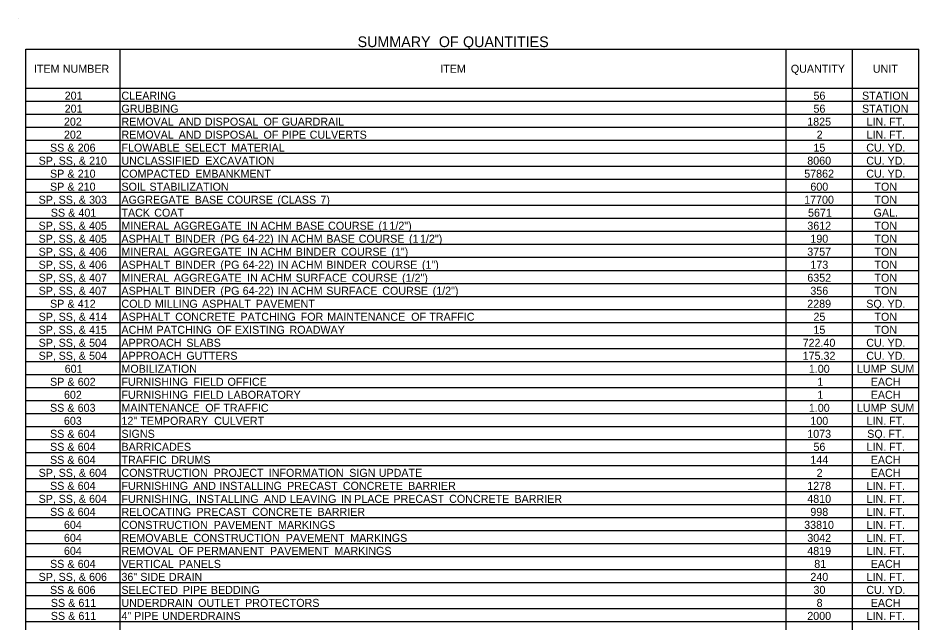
# Model space of a CAD drawing. Extents: x 977434 to 989596, y 1525697 to 1528336.
# Drawn here: x 988121 to 988796, y 1527868 to 1528322 of the extents above; entities that cross this region are included whole.
import ezdxf

# ---------------------------------------------------------------- set-up
doc = ezdxf.new("R2010")
doc.units = 0
doc.layers.add('Default', color=7, linetype='Continuous')
doc.layers.add('R_Border Prem', color=7, linetype='Continuous')

msp = doc.modelspace()

# ---------------------------------------------------------------- linework, layer by layer
at = {"layer": 'Default'}
for p, q in [((988126.95, 1528298.42), (988197.64, 1528298.42)), ((988126.95, 1528298.42), (988796.29, 1528298.42)), ((988126.95, 1527411.17), (988126.95, 1528298.42)), ((988126.95, 1527411.17), (988126.95, 1528298.42)), ((988197.64, 1527625.67), (988197.64, 1528298.42)), ((988696.84, 1527411.17), (988696.84, 1528298.42)), ((988746.57, 1527411.17), (988746.57, 1528298.42)), ((988746.57, 1527625.67), (988746.57, 1528298.42)), ((988796.29, 1527411.17), (988796.29, 1528298.42)), ((988126.95, 1528269.17), (988796.29, 1528269.17)), ((988197.64, 1527625.67), (988197.64, 1528269.17)), ((988696.84, 1527625.67), (988696.84, 1528269.17)), ((988126.95, 1528259.42), (988796.29, 1528259.42)), ((988126.95, 1528249.67), (988796.29, 1528249.67)), ((988126.95, 1528239.92), (988796.29, 1528239.92)), ((988126.95, 1528230.17), (988796.29, 1528230.17)), ((988126.95, 1528220.42), (988796.29, 1528220.42)), ((988126.95, 1528210.67), (988796.29, 1528210.67)), ((988126.95, 1528200.92), (988796.29, 1528200.92)), ((988126.95, 1528191.17), (988796.29, 1528191.17)), ((988126.95, 1528181.42), (988796.29, 1528181.42)), ((988126.95, 1528171.67), (988796.29, 1528171.67)), ((988126.95, 1528161.92), (988796.29, 1528161.92)), ((988126.95, 1528152.17), (988796.29, 1528152.17)), ((988126.95, 1528142.42), (988796.29, 1528142.42)), ((988126.95, 1528132.67), (988796.29, 1528132.67)), ((988126.95, 1528122.92), (988796.29, 1528122.92)), ((988126.95, 1528113.17), (988796.29, 1528113.17)), ((988126.95, 1528103.42), (988796.29, 1528103.42)), ((988126.95, 1528093.67), (988796.29, 1528093.67)), ((988126.95, 1528083.92), (988796.29, 1528083.92)), ((988126.95, 1528074.17), (988796.29, 1528074.17)), ((988126.95, 1528064.42), (988796.29, 1528064.42)), ((988126.95, 1528054.67), (988796.29, 1528054.67)), ((988126.95, 1528044.92), (988796.29, 1528044.92)), ((988126.95, 1528035.17), (988796.29, 1528035.17)), ((988126.95, 1528025.42), (988796.29, 1528025.42)), ((988126.95, 1528015.67), (988796.29, 1528015.67)), ((988126.95, 1528005.92), (988796.29, 1528005.92)), ((988126.95, 1527996.17), (988796.29, 1527996.17)), ((988126.95, 1527986.42), (988796.29, 1527986.42)), ((988126.95, 1527976.67), (988796.29, 1527976.67)), ((988126.95, 1527966.92), (988796.29, 1527966.92)), ((988126.95, 1527957.17), (988796.29, 1527957.17)), ((988126.95, 1527947.42), (988796.29, 1527947.42)), ((988126.95, 1527937.67), (988796.29, 1527937.67)), ((988126.95, 1527927.92), (988796.29, 1527927.92)), ((988126.95, 1527918.17), (988796.29, 1527918.17)), ((988126.95, 1527908.42), (988796.29, 1527908.42)), ((988126.95, 1527898.67), (988796.29, 1527898.67)), ((988126.95, 1527888.92), (988796.29, 1527888.92)), ((988126.95, 1527879.17), (988796.29, 1527879.17)), ((988126.95, 1527869.42), (988796.29, 1527869.42))]:
    msp.add_line(p, q, dxfattribs=at)
at = {"layer": 'R_Border Prem'}
msp.add_line((988121.1, 1528321.82), (988121.1, 1528321.82), dxfattribs=at)

# ---------------------------------------------------------------- texts
at = {"layer": 'Default'}
for s, height, p in [(' SUMMARY', 8, (988372.62, 1528300.02)), (' OF', 8, (988433.5, 1528300.02)), (' QUANTITIES', 8, (988451.61, 1528300.02)), ('ITEM', 6, (988133.04, 1528280.8)), (' NUMBER', 6, (988152.47, 1528280.8)), ('ITEM', 6, (988437.53, 1528280.8)), ('QUANTITY', 6, (988700.27, 1528280.8)), ('UNIT', 6, (988761.74, 1528280.8)), ('201', 6, (988156.08, 1528260.62)), ('CLEARING', 6, (988198.62, 1528260.62)), ('56', 6, (988717.23, 1528260.62)), ('STATION', 6, (988753.6, 1528260.62)), ('201', 6, (988156.08, 1528250.87)), ('GRUBBING', 6, (988198.62, 1528250.87)), ('56', 6, (988717.23, 1528250.87)), ('STATION', 6, (988753.6, 1528250.87)), ('202', 6, (988155.53, 1528241.12)), ('REMOVAL', 6, (988198.62, 1528241.12)), (' AND', 6, (988239.32, 1528241.12)), (' DISPOSAL', 6, (988258.9, 1528241.12)), (' OF', 6, (988302.87, 1528241.12)), (' GUARDRAIL', 6, (988316.45, 1528241.12)), ('1825', 6, (988712.55, 1528241.12)), ('LIN.', 6, (988757.03, 1528241.12)), (' FT.', 6, (988771.66, 1528241.12)), ('202', 6, (988155.53, 1528231.37)), ('REMOVAL', 6, (988198.62, 1528231.37)), (' AND', 6, (988239.32, 1528231.37)), (' DISPOSAL', 6, (988258.9, 1528231.37)), (' OF', 6, (988302.87, 1528231.37)), (' PIPE', 6, (988316.45, 1528231.37)), (' CULVERTS', 6, (988337.44, 1528231.37)), ('2', 6, (988719.6, 1528231.37)), ('LIN.', 6, (988757.03, 1528231.37)), (' FT.', 6, (988771.66, 1528231.37)), ('SS', 6, (988145.1, 1528221.62)), (' &', 6, (988155.84, 1528221.62)), (' 206', 6, (988163.57, 1528221.62)), ('FLOWABLE', 6, (988198.62, 1528221.62)), (' SELECT', 6, (988243.82, 1528221.62)), (' MATERIAL', 6, (988278.6, 1528221.62)), ('15', 6, (988717.21, 1528221.62)), ('CU.', 6, (988756.79, 1528221.62)), (' YD.', 6, (988770.5, 1528221.62)), ('SP,', 6, (988136.55, 1528211.87)), (' SS,', 6, (988149.32, 1528211.87)), (' &', 6, (988164.41, 1528211.87)), (' 210', 6, (988172.14, 1528211.87)), ('UNCLASSIFIED', 6, (988198.62, 1528211.87)), (' EXCAVATION', 6, (988259.2, 1528211.87)), ('8060', 6, (988712.58, 1528211.87)), ('CU.', 6, (988756.79, 1528211.87)), (' YD.', 6, (988770.5, 1528211.87)), ('SP', 6, (988145.07, 1528202.12)), (' &', 6, (988155.89, 1528202.12)), (' 210', 6, (988163.62, 1528202.12)), ('COMPACTED', 6, (988198.62, 1528202.12)), (' EMBANKMENT', 6, (988251.74, 1528202.12)), ('57862', 6, (988710.28, 1528202.12)), ('CU.', 6, (988756.79, 1528202.12)), (' YD.', 6, (988770.5, 1528202.12)), ('SP', 6, (988145.07, 1528192.37)), (' &', 6, (988155.89, 1528192.37)), (' 210', 6, (988163.62, 1528192.37)), ('SOIL', 6, (988198.62, 1528192.37)), (' STABILIZATION', 6, (988217.42, 1528192.37)), ('600', 6, (988714.91, 1528192.37)), ('TON', 6, (988762.92, 1528192.37)), ('SP,', 6, (988136.54, 1528182.62)), (' SS,', 6, (988149.3, 1528182.62)), (' &', 6, (988164.4, 1528182.62)), (' 303', 6, (988172.13, 1528182.62)), ('AGGREGATE', 6, (988198.62, 1528182.62)), (' BASE', 6, (988251.28, 1528182.62)), (' COURSE', 6, (988275.53, 1528182.62)), (' (CLASS', 6, (988313.28, 1528182.62)), (' 7)', 6, (988345.46, 1528182.62)), ('17700', 6, (988710.25, 1528182.62)), ('TON', 6, (988762.92, 1528182.62)), ('SS', 6, (988145.68, 1528172.87)), (' &', 6, (988156.42, 1528172.87)), (' 401', 6, (988164.15, 1528172.87)), ('TACK', 6, (988198.62, 1528172.87)), (' COAT', 6, (988220.96, 1528172.87)), ('5671', 6, (988713.15, 1528172.87)), ('GAL.', 6, (988762.24, 1528172.87)), ('SP,', 6, (988136.51, 1528163.12)), (' SS,', 6, (988149.28, 1528163.12)), (' &', 6, (988164.38, 1528163.12)), (' 405', 6, (988172.11, 1528163.12)), ('MINERAL', 6, (988198.62, 1528163.12)), (' AGGREGATE', 6, (988235.59, 1528163.12)), (' IN', 6, (988290.58, 1528163.12)), (' ACHM', 6, (988300.6, 1528163.12)), (' BASE', 6, (988326.98, 1528163.12)), (' COURSE', 6, (988351.24, 1528163.12)), (' (1', 6, (988388.99, 1528163.12)), (' 1/2")', 6, (988397.22, 1528163.12)), ('3612', 6, (988712.61, 1528163.12)), ('TON', 6, (988762.92, 1528163.12)), ('SP,', 6, (988136.51, 1528153.37)), (' SS,', 6, (988149.28, 1528153.37)), (' &', 6, (988164.38, 1528153.37)), (' 405', 6, (988172.11, 1528153.37)), ('ASPHALT', 6, (988198.62, 1528153.37)), (' BINDER', 6, (988236.66, 1528153.37)), (' (PG', 6, (988270.55, 1528153.37)), (' 64-22)', 6, (988287.25, 1528153.37)), (' IN', 6, (988313.5, 1528153.37)), (' ACHM', 6, (988323.52, 1528153.37)), (' BASE', 6, (988349.91, 1528153.37)), (' COURSE', 6, (988374.16, 1528153.37)), (' (1', 6, (988411.91, 1528153.37)), (' 1/2")', 6, (988420.14, 1528153.37)), ('190', 6, (988714.91, 1528153.37)), ('TON', 6, (988762.92, 1528153.37)), ('SP,', 6, (988136.54, 1528143.62)), (' SS,', 6, (988149.3, 1528143.62)), (' &', 6, (988164.4, 1528143.62)), (' 406', 6, (988172.13, 1528143.62)), ('MINERAL', 6, (988198.62, 1528143.62)), (' AGGREGATE', 6, (988235.59, 1528143.62)), (' IN', 6, (988290.58, 1528143.62)), (' ACHM', 6, (988300.6, 1528143.62)), (' BINDER', 6, (988326.98, 1528143.62)), (' COURSE', 6, (988360.88, 1528143.62)), (' (1")', 6, (988398.63, 1528143.62)), ('3757', 6, (988712.57, 1528143.62)), ('TON', 6, (988762.92, 1528143.62)), ('SP,', 6, (988136.54, 1528133.87)), (' SS,', 6, (988149.3, 1528133.87)), (' &', 6, (988164.4, 1528133.87)), (' 406', 6, (988172.13, 1528133.87)), ('ASPHALT', 6, (988198.62, 1528133.87)), (' BINDER', 6, (988236.66, 1528133.87)), (' (PG', 6, (988270.55, 1528133.87)), (' 64-22)', 6, (988287.25, 1528133.87)), (' IN', 6, (988313.5, 1528133.87)), (' ACHM', 6, (988323.52, 1528133.87)), (' BINDER', 6, (988349.91, 1528133.87)), (' COURSE', 6, (988383.8, 1528133.87)), (' (1")', 6, (988421.55, 1528133.87)), ('173', 6, (988714.9, 1528133.87)), ('TON', 6, (988762.92, 1528133.87)), ('SP,', 6, (988136.54, 1528124.12)), (' SS,', 6, (988149.3, 1528124.12)), (' &', 6, (988164.4, 1528124.12)), (' 407', 6, (988172.13, 1528124.12)), ('MINERAL', 6, (988198.62, 1528124.12)), (' AGGREGATE', 6, (988235.59, 1528124.12)), (' IN', 6, (988290.58, 1528124.12)), (' ACHM', 6, (988300.6, 1528124.12)), (' SURFACE', 6, (988326.98, 1528124.12)), (' COURSE', 6, (988368.93, 1528124.12)), (' (1/2")', 6, (988406.68, 1528124.12)), ('6352', 6, (988712.61, 1528124.12)), ('TON', 6, (988762.92, 1528124.12)), ('SP,', 6, (988136.54, 1528114.37)), (' SS,', 6, (988149.3, 1528114.37)), (' &', 6, (988164.4, 1528114.37)), (' 407', 6, (988172.13, 1528114.37)), ('ASPHALT', 6, (988198.62, 1528114.37)), (' BINDER', 6, (988236.66, 1528114.37)), (' (PG', 6, (988270.55, 1528114.37)), (' 64-22)', 6, (988287.25, 1528114.37)), (' IN', 6, (988313.5, 1528114.37)), (' ACHM', 6, (988323.52, 1528114.37)), (' SURFACE', 6, (988349.91, 1528114.37)), (' COURSE', 6, (988391.85, 1528114.37)), (' (1/2")', 6, (988429.6, 1528114.37)), ('356', 6, (988714.9, 1528114.37)), ('TON', 6, (988762.92, 1528114.37)), ('SP', 6, (988145.09, 1528104.62)), (' &', 6, (988155.91, 1528104.62)), (' 412', 6, (988163.64, 1528104.62)), ('COLD', 6, (988198.62, 1528104.62)), (' MILLING', 6, (988221.46, 1528104.62)), (' ASPHALT', 6, (988256.8, 1528104.62)), (' PAVEMENT', 6, (988297.16, 1528104.62)), ('2289', 6, (988712.57, 1528104.62)), ('SQ.', 6, (988756.79, 1528104.62)), (' YD.', 6, (988770.5, 1528104.62)), ('SP,', 6, (988136.55, 1528094.87)), (' SS,', 6, (988149.32, 1528094.87)), (' &', 6, (988164.41, 1528094.87)), (' 414', 6, (988172.14, 1528094.87)), ('ASPHALT', 6, (988198.62, 1528094.87)), (' CONCRETE', 6, (988236.66, 1528094.87)), (' PATCHING', 6, (988285.58, 1528094.87)), (' FOR', 6, (988330.71, 1528094.87)), (' MAINTENANCE', 6, (988350.62, 1528094.87)), (' OF', 6, (988413.52, 1528094.87)), (' TRAFFIC', 6, (988427.11, 1528094.87)), ('25', 6, (988717.21, 1528094.87)), ('TON', 6, (988762.92, 1528094.87)), ('SP,', 6, (988136.51, 1528085.12)), (' SS,', 6, (988149.28, 1528085.12)), (' &', 6, (988164.38, 1528085.12)), (' 415', 6, (988172.11, 1528085.12)), ('ACHM', 6, (988198.62, 1528085.12)), (' PATCHING', 6, (988222.67, 1528085.12)), (' OF', 6, (988267.79, 1528085.12)), (' EXISTING', 6, (988281.38, 1528085.12)), (' ROADWAY', 6, (988322.32, 1528085.12)), ('15', 6, (988717.21, 1528085.12)), ('TON', 6, (988762.92, 1528085.12)), ('SP,', 6, (988136.55, 1528075.37)), (' SS,', 6, (988149.32, 1528075.37)), (' &', 6, (988164.41, 1528075.37)), (' 504', 6, (988172.14, 1528075.37)), ('APPROACH', 6, (988198.62, 1528075.37)), (' SLABS', 6, (988245, 1528075.37)), ('722.40', 6, (988709.09, 1528075.37)), ('CU.', 6, (988756.79, 1528075.37)), (' YD.', 6, (988770.5, 1528075.37)), ('SP,', 6, (988136.55, 1528065.62)), (' SS,', 6, (988149.32, 1528065.62)), (' &', 6, (988164.41, 1528065.62)), (' 504', 6, (988172.14, 1528065.62)), ('APPROACH', 6, (988198.62, 1528065.62)), (' GUTTERS', 6, (988245, 1528065.62)), ('175.32', 6, (988709.11, 1528065.62)), ('CU.', 6, (988756.79, 1528065.62)), (' YD.', 6, (988770.5, 1528065.62)), ('601', 6, (988156.08, 1528055.87)), ('MOBILIZATION', 6, (988198.62, 1528055.87)), ('1.00', 6, (988713.75, 1528055.87)), ('LUMP', 6, (988749.8, 1528055.87)), (' SUM', 6, (988772.73, 1528055.87)), ('SP', 6, (988145.09, 1528046.12)), (' &', 6, (988155.91, 1528046.12)), (' 602', 6, (988163.64, 1528046.12)), ('FURNISHING', 6, (988198.62, 1528046.12)), (' FIELD', 6, (988250.26, 1528046.12)), (' OFFICE', 6, (988275.89, 1528046.12)), ('1', 6, (988720.14, 1528046.12)), ('EACH', 6, (988760.12, 1528046.12)), ('602', 6, (988155.53, 1528036.37)), ('FURNISHING', 6, (988198.62, 1528036.37)), (' FIELD', 6, (988250.26, 1528036.37)), (' LABORATORY', 6, (988275.89, 1528036.37)), ('1', 6, (988720.14, 1528036.37)), ('EACH', 6, (988760.12, 1528036.37)), ('SS', 6, (988145.1, 1528026.62)), (' &', 6, (988155.84, 1528026.62)), (' 603', 6, (988163.57, 1528026.62)), ('MAINTENANCE', 6, (988198.62, 1528026.62)), (' OF', 6, (988259.19, 1528026.62)), (' TRAFFIC', 6, (988272.78, 1528026.62)), ('1.00', 6, (988713.75, 1528026.62)), ('LUMP', 6, (988749.8, 1528026.62)), (' SUM', 6, (988772.73, 1528026.62)), ('603', 6, (988155.5, 1528016.87)), ('12"', 6, (988198.62, 1528016.87)), (' TEMPORARY', 6, (988210.52, 1528016.87)), (' CULVERT', 6, (988265.89, 1528016.87)), ('100', 6, (988714.91, 1528016.87)), ('LIN.', 6, (988757.03, 1528016.87)), (' FT.', 6, (988771.66, 1528016.87)), ('SS', 6, (988145.11, 1528007.12)), (' &', 6, (988155.86, 1528007.12)), (' 604', 6, (988163.58, 1528007.12)), ('SIGNS', 6, (988198.62, 1528007.12)), ('1073', 6, (988712.57, 1528007.12)), ('SQ.', 6, (988757.49, 1528007.12)), (' FT.', 6, (988771.2, 1528007.12)), ('SS', 6, (988145.11, 1527997.37)), (' &', 6, (988155.86, 1527997.37)), (' 604', 6, (988163.58, 1527997.37)), ('BARRICADES', 6, (988198.62, 1527997.37)), ('56', 6, (988717.23, 1527997.37)), ('LIN.', 6, (988757.03, 1527997.37)), (' FT.', 6, (988771.66, 1527997.37)), ('SS', 6, (988145.11, 1527987.62)), (' &', 6, (988155.86, 1527987.62)), (' 604', 6, (988163.58, 1527987.62)), ('TRAFFIC', 6, (988198.62, 1527987.62)), (' DRUMS', 6, (988233.68, 1527987.62)), ('144', 6, (988714.92, 1527987.62)), ('EACH', 6, (988760.12, 1527987.62)), ('SP,', 6, (988136.55, 1527977.87)), (' SS,', 6, (988149.32, 1527977.87)), (' &', 6, (988164.41, 1527977.87)), (' 604', 6, (988172.14, 1527977.87)), ('CONSTRUCTION', 6, (988198.62, 1527977.87)), (' PROJECT', 6, (988265.47, 1527977.87)), (' INFORMATION', 6, (988306.76, 1527977.87)), (' SIGN', 6, (988367.08, 1527977.87)), (' UPDATE', 6, (988389.22, 1527977.87)), ('2', 6, (988719.6, 1527977.87)), ('EACH', 6, (988760.12, 1527977.87)), ('SS', 6, (988145.11, 1527968.12)), (' &', 6, (988155.86, 1527968.12)), (' 604', 6, (988163.58, 1527968.12)), ('FURNISHING', 6, (988198.62, 1527968.12)), (' AND', 6, (988250.26, 1527968.12)), (' INSTALLING', 6, (988269.84, 1527968.12)), (' PRECAST', 6, (988320.55, 1527968.12)), (' CONCRETE', 6, (988362.32, 1527968.12)), (' BARRIER', 6, (988411.25, 1527968.12)), ('1278', 6, (988712.57, 1527968.12)), ('LIN.', 6, (988757.03, 1527968.12)), (' FT.', 6, (988771.66, 1527968.12)), ('SP,', 6, (988136.55, 1527958.37)), (' SS,', 6, (988149.32, 1527958.37)), (' &', 6, (988164.41, 1527958.37)), (' 604', 6, (988172.14, 1527958.37)), ('FURNISHING,', 6, (988198.62, 1527958.37)), (' INSTALLING', 6, (988252.36, 1527958.37)), (' AND', 6, (988303.08, 1527958.37)), (' LEAVING', 6, (988322.66, 1527958.37)), (' IN', 6, (988360.81, 1527958.37)), (' PLACE', 6, (988370.83, 1527958.37)), (' PRECAST', 6, (988400.21, 1527958.37)), (' CONCRETE', 6, (988441.97, 1527958.37)), (' BARRIER', 6, (988490.9, 1527958.37)), ('4810', 6, (988712.58, 1527958.37)), ('LIN.', 6, (988757.03, 1527958.37)), (' FT.', 6, (988771.66, 1527958.37)), ('SS', 6, (988145.11, 1527948.62)), (' &', 6, (988155.86, 1527948.62)), (' 604', 6, (988163.58, 1527948.62)), ('RELOCATING', 6, (988198.62, 1527948.62)), (' PRECAST', 6, (988252.59, 1527948.62)), (' CONCRETE', 6, (988294.36, 1527948.62)), (' BARRIER', 6, (988343.28, 1527948.62)), ('998', 6, (988714.9, 1527948.62)), ('LIN.', 6, (988757.03, 1527948.62)), (' FT.', 6, (988771.66, 1527948.62)), ('604', 6, (988155.51, 1527938.87)), ('CONSTRUCTION', 6, (988198.62, 1527938.87)), (' PAVEMENT', 6, (988265.47, 1527938.87)), (' MARKINGS', 6, (988313.75, 1527938.87)), ('33810', 6, (988710.25, 1527938.87)), ('LIN.', 6, (988757.03, 1527938.87)), (' FT.', 6, (988771.66, 1527938.87)), ('604', 6, (988155.51, 1527929.12)), ('REMOVABLE', 6, (988198.62, 1527929.12)), (' CONSTRUCTION', 6, (988250.35, 1527929.12)), (' PAVEMENT', 6, (988319.53, 1527929.12)), (' MARKINGS', 6, (988367.81, 1527929.12)), ('3042', 6, (988712.61, 1527929.12)), ('LIN.', 6, (988757.03, 1527929.12)), (' FT.', 6, (988771.66, 1527929.12)), ('604', 6, (988155.51, 1527919.37)), ('REMOVAL', 6, (988198.62, 1527919.37)), (' OF', 6, (988239.32, 1527919.37)), (' PERMANENT', 6, (988252.9, 1527919.37)), (' PAVEMENT', 6, (988307.7, 1527919.37)), (' MARKINGS', 6, (988355.99, 1527919.37)), ('4819', 6, (988712.57, 1527919.37)), ('LIN.', 6, (988757.03, 1527919.37)), (' FT.', 6, (988771.66, 1527919.37)), ('SS', 6, (988145.11, 1527909.62)), (' &', 6, (988155.86, 1527909.62)), (' 604', 6, (988163.58, 1527909.62)), ('VERTICAL', 6, (988198.62, 1527909.62)), (' PANELS', 6, (988239.32, 1527909.62)), ('81', 6, (988717.81, 1527909.62)), ('EACH', 6, (988760.12, 1527909.62)), ('SP,', 6, (988136.54, 1527899.87)), (' SS,', 6, (988149.3, 1527899.87)), (' &', 6, (988164.4, 1527899.87)), (' 606', 6, (988172.13, 1527899.87)), ('36"', 6, (988198.62, 1527899.87)), (' SIDE', 6, (988210.52, 1527899.87)), (' DRAIN', 6, (988231.97, 1527899.87)), ('240', 6, (988714.91, 1527899.87)), ('LIN.', 6, (988757.03, 1527899.87)), (' FT.', 6, (988771.66, 1527899.87)), ('SS', 6, (988145.1, 1527890.12)), (' &', 6, (988155.84, 1527890.12)), (' 606', 6, (988163.57, 1527890.12)), ('SELECTED', 6, (988198.62, 1527890.12)), (' PIPE', 6, (988242.43, 1527890.12)), (' BEDDING', 6, (988263.42, 1527890.12)), ('30', 6, (988717.24, 1527890.12)), ('CU.', 6, (988756.79, 1527890.12)), (' YD.', 6, (988770.5, 1527890.12)), ('SS', 6, (988145.68, 1527880.37)), (' &', 6, (988156.42, 1527880.37)), (' 611', 6, (988164.15, 1527880.37)), ('UNDERDRAIN', 6, (988198.62, 1527880.37)), (' OUTLET', 6, (988253.83, 1527880.37)), (' PROTECTORS', 6, (988289.06, 1527880.37)), ('8', 6, (988719.56, 1527880.37)), ('EACH', 6, (988760.12, 1527880.37)), ('SS', 6, (988145.68, 1527870.62)), (' &', 6, (988156.42, 1527870.62)), (' 611', 6, (988164.15, 1527870.62)), ('4"', 6, (988198.62, 1527870.62)), (' PIPE', 6, (988205.86, 1527870.62)), (' UNDERDRAINS', 6, (988226.85, 1527870.62)), ('2000', 6, (988712.58, 1527870.62)), ('LIN.', 6, (988757.03, 1527870.62)), (' FT.', 6, (988771.66, 1527870.62))]:
    msp.add_text(s, height=height, dxfattribs=at).set_placement(p)

doc.saveas('drawing.dxf')
